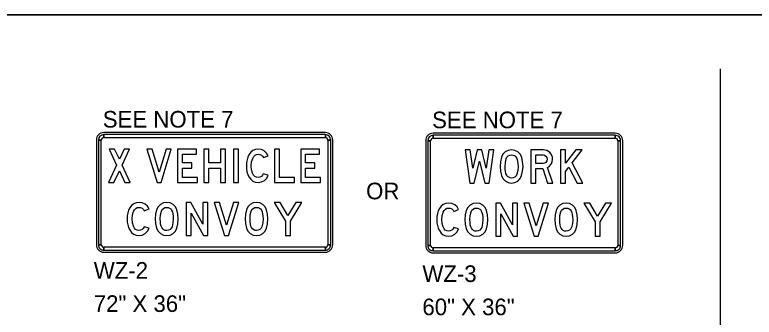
# Model space of a CAD drawing. Extents: x 1416408 to 1429341, y 372694 to 383211.
# Drawn here: x 1427672.1 to 1428119.8, y 374297 to 374479.9 of the extents above; entities that cross this region are included whole.
import ezdxf

# ---------------------------------------------------------------- set-up
doc = ezdxf.new("R2010")
doc.units = 0
for name, color, linetype in [('Default', 7, 'Continuous'), ('DSN_DRFT_Junk-No-Plot', 7, 'Continuous'), ('Working Level 1', 7, 'Continuous')]:
    doc.layers.add(name, color=color, linetype=linetype)

msp = doc.modelspace()

# ---------------------------------------------------------------- linework, layer by layer
at = {"layer": 'Default'}
for points in [[(1426234.86, 374479.9), (1426234.86, 372693.86), (1428995.11, 372693.86), (1428995.11, 374479.9)], [(1426234.86, 374479.9), (1426234.86, 372693.86), (1428995.11, 372693.86), (1428995.11, 374479.9)], [(1426234.86, 374479.9), (1428995.11, 374479.9), (1428995.11, 372693.86), (1426234.86, 372693.86)], [(1426234.86, 374479.9), (1426234.86, 372693.86), (1428995.11, 372693.86), (1428995.11, 374479.9)]]:
    msp.add_lwpolyline(points, close=True, dxfattribs=at)
at = {"layer": 'DSN_DRFT_Junk-No-Plot'}
msp.add_lwpolyline([(1426234.86, 374479.9), (1428995.11, 374479.9), (1428995.11, 372693.86), (1426234.86, 372693.86)], close=True, dxfattribs=at)
at = {"layer": 'Working Level 1'}
for p, q in [((1428099.08, 374447.3), (1428099.08, 372727.17)), ((1427860.12, 374408.67), (1427725.97, 374408.67)), ((1428035.67, 374408.28), (1427925.37, 374408.28)), ((1427721.5, 374404.15), (1427721.5, 374340.86)), ((1427722.74, 374404.15), (1427724.48, 374404.15)), ((1427725.97, 374405.66), (1427725.97, 374407.42)), ((1427860.12, 374407.42), (1427860.12, 374405.66)), ((1427861.61, 374404.15), (1427863.35, 374404.15)), ((1427864.59, 374340.86), (1427864.59, 374404.15)), ((1427920.9, 374403.76), (1427920.9, 374340.47)), ((1427922.14, 374403.76), (1427923.88, 374403.76)), ((1427925.37, 374405.27), (1427925.37, 374407.02)), ((1428035.67, 374407.02), (1428035.67, 374405.27)), ((1428037.16, 374403.76), (1428038.9, 374403.76)), ((1428040.14, 374340.47), (1428040.14, 374403.76)), ((1427724.48, 374340.86), (1427722.74, 374340.86)), ((1427863.35, 374340.86), (1427861.61, 374340.86)), ((1427725.97, 374337.6), (1427725.97, 374339.35)), ((1427725.97, 374336.34), (1427860.12, 374336.34)), ((1427860.12, 374339.35), (1427860.12, 374337.6)), ((1427923.88, 374340.47), (1427922.14, 374340.47)), ((1427925.37, 374337.2), (1427925.37, 374338.96)), ((1428035.67, 374338.96), (1428035.67, 374337.2)), ((1428038.9, 374340.47), (1428037.16, 374340.47)), ((1427925.37, 374335.95), (1428035.67, 374335.95))]:
    msp.add_line(p, q, dxfattribs=at)
for points in [[(1427722.74, 374404.15), (1427722.74, 374340.86), (1427724.48, 374340.86), (1427724.48, 374404.15), (1427722.74, 374404.15)], [(1427860.12, 374407.42), (1427725.97, 374407.42), (1427725.97, 374405.66), (1427860.12, 374405.66), (1427860.12, 374407.42)], [(1427863.35, 374340.86), (1427863.35, 374404.15), (1427861.61, 374404.15), (1427861.61, 374340.86), (1427863.35, 374340.86)], [(1427922.14, 374403.76), (1427922.14, 374340.47), (1427923.88, 374340.47), (1427923.88, 374403.76), (1427922.14, 374403.76)], [(1428035.67, 374407.02), (1427925.37, 374407.02), (1427925.37, 374405.27), (1428035.67, 374405.27), (1428035.67, 374407.02)], [(1428038.9, 374340.47), (1428038.9, 374403.76), (1428037.16, 374403.76), (1428037.16, 374340.47), (1428038.9, 374340.47)], [(1427742.03, 374378.53), (1427737.08, 374389.05), (1427741.62, 374398.62), (1427738.3, 374398.62), (1427735.42, 374392.56), (1427732.56, 374398.62), (1427729.23, 374398.62), (1427733.75, 374389.03), (1427728.77, 374378.53), (1427732.09, 374378.53), (1427735.4, 374385.52), (1427738.71, 374378.53)], [(1427766.85, 374398.62), (1427763.71, 374398.62), (1427759.45, 374384.74), (1427755.19, 374398.62), (1427752.05, 374398.62), (1427758.21, 374378.53), (1427760.68, 374378.53)], [(1427782.7, 374381.57), (1427773.68, 374381.57), (1427773.68, 374387.25), (1427779.31, 374387.25), (1427779.31, 374390.28), (1427773.68, 374390.28), (1427773.68, 374395.59), (1427782.09, 374395.59), (1427782.09, 374398.62), (1427770.69, 374398.62), (1427770.69, 374378.53), (1427782.7, 374378.53)], [(1427799.64, 374378.53), (1427799.64, 374398.62), (1427796.65, 374398.62), (1427796.65, 374390.28), (1427789.52, 374390.28), (1427789.52, 374398.62), (1427786.52, 374398.62), (1427786.52, 374378.53), (1427789.52, 374378.53), (1427789.52, 374387.25), (1427796.65, 374387.25), (1427796.65, 374378.53)], [(1427807.53, 374378.53), (1427807.53, 374398.62), (1427804.53, 374398.62), (1427804.53, 374378.53)], [(1427825.56, 374382.99), (1427822.55, 374383.76), (1427822.11, 374382.88), (1427821.38, 374382.18), (1427820.45, 374381.72), (1427819.42, 374381.57), (1427818.37, 374381.72), (1427817.47, 374382.21), (1427816.72, 374383), (1427816.11, 374384.12), (1427815.49, 374386.19), (1427815.3, 374388.58), (1427815.5, 374390.98), (1427816.13, 374393.05), (1427816.76, 374394.16), (1427817.54, 374394.95), (1427818.45, 374395.43), (1427819.51, 374395.59), (1427820.5, 374395.45), (1427821.41, 374395.04), (1427822.16, 374394.38), (1427822.68, 374393.54), (1427825.56, 374394.68), (1427824.59, 374396.29), (1427823.17, 374397.55), (1427821.45, 374398.35), (1427819.56, 374398.62), (1427817.81, 374398.41), (1427816.29, 374397.78), (1427814.98, 374396.73), (1427813.9, 374395.27), (1427813.19, 374393.82), (1427812.7, 374392.23), (1427812.4, 374390.48), (1427812.3, 374388.59), (1427812.39, 374386.7), (1427812.69, 374384.96), (1427813.18, 374383.37), (1427813.88, 374381.92), (1427814.94, 374380.43), (1427816.23, 374379.38), (1427817.73, 374378.74), (1427819.46, 374378.53), (1427821.48, 374378.84), (1427823.3, 374379.77), (1427824.72, 374381.2)], [(1427841.39, 374378.53), (1427841.39, 374381.57), (1427832.37, 374381.57), (1427832.37, 374398.62), (1427829.38, 374398.62), (1427829.38, 374378.53)], [(1427857.23, 374381.57), (1427848.21, 374381.57), (1427848.21, 374387.25), (1427853.84, 374387.25), (1427853.84, 374390.28), (1427848.21, 374390.28), (1427848.21, 374395.59), (1427856.62, 374395.59), (1427856.62, 374398.62), (1427845.21, 374398.62), (1427845.21, 374378.53), (1427857.23, 374378.53)], [(1427962.08, 374398.23), (1427959.05, 374398.23), (1427957.52, 374387.23), (1427954.89, 374398.23), (1427951.99, 374398.23), (1427949.37, 374387.21), (1427947.85, 374398.23), (1427944.81, 374398.23), (1427947.59, 374378.14), (1427950.3, 374378.14), (1427953.44, 374391.36), (1427956.59, 374378.14), (1427959.29, 374378.14)], [(1427979.8, 374388.2), (1427979.59, 374391.07), (1427978.99, 374393.75), (1427978.09, 374395.56), (1427976.67, 374397), (1427974.87, 374397.92), (1427972.85, 374398.23), (1427970.83, 374397.92), (1427969.04, 374397), (1427967.62, 374395.56), (1427966.73, 374393.73), (1427966.12, 374391.05), (1427965.93, 374388.2), (1427966.12, 374385.35), (1427966.73, 374382.66), (1427967.62, 374380.84), (1427969.04, 374379.4), (1427970.83, 374378.45), (1427972.85, 374378.14), (1427974.87, 374378.45), (1427976.66, 374379.38), (1427978.07, 374380.81), (1427978.97, 374382.63), (1427979.59, 374385.32)], [(1427976.8, 374388.19), (1427976.62, 374385.75), (1427976.1, 374383.48), (1427975.61, 374382.53), (1427974.87, 374381.8), (1427973.93, 374381.33), (1427972.87, 374381.17), (1427971.94, 374381.28), (1427971.14, 374381.61), (1427970.46, 374382.16), (1427969.91, 374382.93), (1427969.47, 374383.91), (1427969.17, 374385.12), (1427968.98, 374386.54), (1427968.92, 374388.19), (1427969.1, 374390.62), (1427969.63, 374392.88), (1427970.1, 374393.83), (1427970.85, 374394.57), (1427971.79, 374395.04), (1427972.87, 374395.2), (1427973.79, 374395.09), (1427974.58, 374394.76), (1427975.26, 374394.21), (1427975.81, 374393.45), (1427976.24, 374392.46), (1427976.55, 374391.26), (1427976.73, 374389.83)], [(1427997.82, 374378.14), (1427994.68, 374387.52), (1427995.91, 374388.39), (1427996.86, 374389.6), (1427997.47, 374391.04), (1427997.68, 374392.59), (1427997.57, 374393.71), (1427997.26, 374394.74), (1427996.75, 374395.7), (1427996.03, 374396.57), (1427995.15, 374397.3), (1427994.2, 374397.82), (1427993.17, 374398.13), (1427992.06, 374398.23), (1427984.56, 374398.23), (1427984.56, 374378.14), (1427987.56, 374378.14), (1427987.56, 374386.86), (1427991.72, 374386.86), (1427994.66, 374378.14)], [(1427987.56, 374389.89), (1427987.56, 374395.2), (1427991.93, 374395.2), (1427992.88, 374395), (1427993.69, 374394.41), (1427994.23, 374393.55), (1427994.42, 374392.55), (1427994.23, 374391.52), (1427993.69, 374390.67), (1427992.88, 374390.08), (1427991.93, 374389.89)], [(1428016.03, 374378.14), (1428009.57, 374390.38), (1428015.55, 374398.23), (1428011.76, 374398.23), (1428005.57, 374390.09), (1428005.57, 374398.23), (1428002.57, 374398.23), (1428002.57, 374378.14), (1428005.57, 374378.14), (1428005.57, 374385.12), (1428007.57, 374387.74), (1428012.63, 374378.14)], [(1427753.36, 374350.84), (1427750.36, 374351.61), (1427749.91, 374350.73), (1427749.19, 374350.03), (1427748.25, 374349.57), (1427747.22, 374349.42), (1427746.17, 374349.58), (1427745.28, 374350.06), (1427744.52, 374350.86), (1427743.91, 374351.98), (1427743.3, 374354.04), (1427743.1, 374356.43), (1427743.3, 374358.84), (1427743.94, 374360.9), (1427744.56, 374362.01), (1427745.34, 374362.8), (1427746.25, 374363.28), (1427747.32, 374363.44), (1427748.31, 374363.3), (1427749.21, 374362.89), (1427749.97, 374362.23), (1427750.48, 374361.39), (1427753.36, 374362.53), (1427752.39, 374364.14), (1427750.97, 374365.4), (1427749.25, 374366.2), (1427747.36, 374366.48), (1427745.61, 374366.26), (1427744.09, 374365.64), (1427742.78, 374364.59), (1427741.7, 374363.13), (1427741, 374361.67), (1427740.5, 374360.08), (1427740.2, 374358.33), (1427740.1, 374356.44), (1427740.19, 374354.55), (1427740.49, 374352.81), (1427740.98, 374351.22), (1427741.68, 374349.77), (1427742.74, 374348.29), (1427744.03, 374347.23), (1427745.54, 374346.59), (1427747.26, 374346.39), (1427749.28, 374346.69), (1427751.1, 374347.62), (1427752.52, 374349.05)], [(1427771.05, 374356.44), (1427770.85, 374359.31), (1427770.24, 374361.99), (1427769.35, 374363.8), (1427767.92, 374365.24), (1427766.12, 374366.16), (1427764.1, 374366.48), (1427762.08, 374366.16), (1427760.29, 374365.24), (1427758.88, 374363.8), (1427757.99, 374361.98), (1427757.38, 374359.29), (1427757.18, 374356.44), (1427757.38, 374353.59), (1427757.99, 374350.9), (1427758.88, 374349.08), (1427760.29, 374347.64), (1427762.08, 374346.7), (1427764.1, 374346.39), (1427766.12, 374346.69), (1427767.91, 374347.62), (1427769.33, 374349.05), (1427770.23, 374350.87), (1427770.84, 374353.56)], [(1427768.05, 374356.43), (1427767.87, 374353.99), (1427767.35, 374351.72), (1427766.87, 374350.77), (1427766.12, 374350.04), (1427765.19, 374349.57), (1427764.13, 374349.42), (1427763.2, 374349.52), (1427762.39, 374349.86), (1427761.71, 374350.4), (1427761.16, 374351.17), (1427760.73, 374352.15), (1427760.42, 374353.36), (1427760.24, 374354.78), (1427760.18, 374356.43), (1427760.35, 374358.86), (1427760.88, 374361.12), (1427761.35, 374362.07), (1427762.1, 374362.81), (1427763.04, 374363.28), (1427764.13, 374363.44), (1427765.04, 374363.33), (1427765.84, 374363.01), (1427766.51, 374362.46), (1427767.07, 374361.69), (1427767.49, 374360.7), (1427767.8, 374359.5), (1427767.99, 374358.07)], [(1427788.93, 374346.39), (1427788.93, 374366.48), (1427785.93, 374366.48), (1427785.93, 374353.27), (1427778.69, 374366.48), (1427775.81, 374366.48), (1427775.81, 374346.39), (1427778.81, 374346.39), (1427778.81, 374360.02), (1427786.29, 374346.39)], [(1427807.69, 374366.48), (1427804.55, 374366.48), (1427800.28, 374352.59), (1427796.02, 374366.48), (1427792.89, 374366.48), (1427799.05, 374346.39), (1427801.51, 374346.39)], [(1427825.39, 374356.44), (1427825.19, 374359.31), (1427824.58, 374361.99), (1427823.69, 374363.8), (1427822.26, 374365.24), (1427820.46, 374366.16), (1427818.44, 374366.48), (1427816.42, 374366.16), (1427814.64, 374365.24), (1427813.22, 374363.8), (1427812.33, 374361.98), (1427811.72, 374359.29), (1427811.52, 374356.44), (1427811.72, 374353.59), (1427812.33, 374350.9), (1427813.22, 374349.08), (1427814.64, 374347.64), (1427816.42, 374346.7), (1427818.44, 374346.39), (1427820.46, 374346.69), (1427822.25, 374347.62), (1427823.67, 374349.05), (1427824.57, 374350.87), (1427825.18, 374353.56)], [(1427822.39, 374356.43), (1427822.22, 374353.99), (1427821.69, 374351.72), (1427821.21, 374350.77), (1427820.46, 374350.04), (1427819.53, 374349.57), (1427818.47, 374349.42), (1427817.54, 374349.52), (1427816.73, 374349.86), (1427816.05, 374350.4), (1427815.5, 374351.17), (1427815.07, 374352.15), (1427814.76, 374353.36), (1427814.58, 374354.78), (1427814.52, 374356.43), (1427814.69, 374358.86), (1427815.22, 374361.12), (1427815.7, 374362.07), (1427816.44, 374362.81), (1427817.38, 374363.28), (1427818.47, 374363.44), (1427819.38, 374363.33), (1427820.18, 374363.01), (1427820.85, 374362.46), (1427821.41, 374361.69), (1427821.84, 374360.7), (1427822.15, 374359.5), (1427822.33, 374358.07)], [(1427845.88, 374366.48), (1427842.35, 374366.48), (1427837.48, 374358.46), (1427832.71, 374366.48), (1427829.22, 374366.48), (1427835.97, 374355.19), (1427835.97, 374346.39), (1427838.97, 374346.39), (1427838.97, 374355.11)], [(1427940.84, 374350.45), (1427937.83, 374351.22), (1427937.39, 374350.34), (1427936.66, 374349.64), (1427935.73, 374349.18), (1427934.69, 374349.03), (1427933.65, 374349.19), (1427932.75, 374349.67), (1427932, 374350.47), (1427931.39, 374351.58), (1427930.77, 374353.65), (1427930.58, 374356.04), (1427930.78, 374358.44), (1427931.41, 374360.51), (1427932.04, 374361.62), (1427932.81, 374362.41), (1427933.73, 374362.89), (1427934.79, 374363.05), (1427935.78, 374362.91), (1427936.69, 374362.5), (1427937.44, 374361.84), (1427937.96, 374361), (1427940.84, 374362.14), (1427939.87, 374363.75), (1427938.45, 374365.01), (1427936.73, 374365.81), (1427934.84, 374366.08), (1427933.09, 374365.87), (1427931.56, 374365.25), (1427930.26, 374364.2), (1427929.18, 374362.73), (1427928.47, 374361.28), (1427927.97, 374359.69), (1427927.68, 374357.94), (1427927.58, 374356.05), (1427927.67, 374354.16), (1427927.97, 374352.42), (1427928.46, 374350.83), (1427929.16, 374349.38), (1427930.22, 374347.9), (1427931.51, 374346.84), (1427933.01, 374346.2), (1427934.74, 374345.99), (1427936.76, 374346.3), (1427938.58, 374347.23), (1427940, 374348.66)], [(1427958.53, 374356.05), (1427958.32, 374358.92), (1427957.72, 374361.6), (1427956.82, 374363.41), (1427955.4, 374364.85), (1427953.6, 374365.77), (1427951.58, 374366.08), (1427949.56, 374365.77), (1427947.77, 374364.85), (1427946.35, 374363.41), (1427945.46, 374361.58), (1427944.85, 374358.9), (1427944.66, 374356.05), (1427944.85, 374353.2), (1427945.46, 374350.51), (1427946.35, 374348.69), (1427947.77, 374347.25), (1427949.56, 374346.31), (1427951.58, 374345.99), (1427953.6, 374346.3), (1427955.39, 374347.23), (1427956.8, 374348.66), (1427957.7, 374350.48), (1427958.32, 374353.17)], [(1427955.53, 374356.04), (1427955.35, 374353.6), (1427954.83, 374351.33), (1427954.34, 374350.38), (1427953.6, 374349.65), (1427952.66, 374349.18), (1427951.6, 374349.03), (1427950.67, 374349.13), (1427949.87, 374349.46), (1427949.19, 374350.01), (1427948.64, 374350.78), (1427948.2, 374351.76), (1427947.9, 374352.97), (1427947.71, 374354.39), (1427947.65, 374356.04), (1427947.83, 374358.47), (1427948.36, 374360.73), (1427948.83, 374361.68), (1427949.58, 374362.42), (1427950.52, 374362.89), (1427951.6, 374363.05), (1427952.52, 374362.94), (1427953.31, 374362.61), (1427953.99, 374362.06), (1427954.54, 374361.3), (1427954.97, 374360.31), (1427955.28, 374359.11), (1427955.46, 374357.68)], [(1427976.41, 374345.99), (1427976.41, 374366.08), (1427973.41, 374366.08), (1427973.41, 374352.88), (1427966.17, 374366.08), (1427963.29, 374366.08), (1427963.29, 374345.99), (1427966.29, 374345.99), (1427966.29, 374359.62), (1427973.76, 374345.99)], [(1427995.16, 374366.08), (1427992.02, 374366.08), (1427987.76, 374352.2), (1427983.5, 374366.08), (1427980.37, 374366.08), (1427986.52, 374345.99), (1427988.99, 374345.99)], [(1428012.87, 374356.05), (1428012.66, 374358.92), (1428012.06, 374361.6), (1428011.17, 374363.41), (1428009.74, 374364.85), (1428007.94, 374365.77), (1428005.92, 374366.08), (1428003.9, 374365.77), (1428002.11, 374364.85), (1428000.69, 374363.41), (1427999.8, 374361.58), (1427999.2, 374358.9), (1427999, 374356.05), (1427999.2, 374353.2), (1427999.8, 374350.51), (1428000.69, 374348.69), (1428002.11, 374347.25), (1428003.9, 374346.31), (1428005.92, 374345.99), (1428007.94, 374346.3), (1428009.73, 374347.23), (1428011.15, 374348.66), (1428012.04, 374350.48), (1428012.66, 374353.17)], [(1428009.87, 374356.04), (1428009.69, 374353.6), (1428009.17, 374351.33), (1428008.69, 374350.38), (1428007.94, 374349.65), (1428007, 374349.18), (1428005.94, 374349.03), (1428005.01, 374349.13), (1428004.21, 374349.46), (1428003.53, 374350.01), (1428002.98, 374350.78), (1428002.55, 374351.76), (1428002.24, 374352.97), (1428002.05, 374354.39), (1428002, 374356.04), (1428002.17, 374358.47), (1428002.7, 374360.73), (1428003.17, 374361.68), (1428003.92, 374362.42), (1428004.86, 374362.89), (1428005.94, 374363.05), (1428006.86, 374362.94), (1428007.65, 374362.61), (1428008.33, 374362.06), (1428008.88, 374361.3), (1428009.31, 374360.31), (1428009.62, 374359.11), (1428009.8, 374357.68)], [(1428033.35, 374366.08), (1428029.83, 374366.08), (1428024.96, 374358.06), (1428020.19, 374366.08), (1428016.7, 374366.08), (1428023.44, 374354.79), (1428023.44, 374345.99), (1428026.44, 374345.99), (1428026.44, 374354.71)], [(1427725.97, 374337.6), (1427860.12, 374337.6), (1427860.12, 374339.35), (1427725.97, 374339.35), (1427725.97, 374337.6)], [(1427925.37, 374337.2), (1428035.67, 374337.2), (1428035.67, 374338.96), (1427925.37, 374338.96), (1427925.37, 374337.2)]]:
    msp.add_lwpolyline(points, close=True, dxfattribs=at)
for centre, major_axis, start_param, end_param in [((1427725.97, 374404.15), (0, 4.52), 0.000004, 1.570794), ((1427860.12, 374404.15), (0, 4.52), 4.712389, 6.283189), ((1427925.37, 374403.76), (0, 4.52), 0.000004, 1.570794), ((1428035.67, 374403.76), (0, 4.52), 4.712389, 6.283189), ((1427725.97, 374404.15), (0, 3.27), 0.000004, 1.570794), ((1427725.97, 374404.15), (0, 1.51), 0.000004, 1.570794), ((1427860.12, 374404.15), (0, 3.27), 4.712389, 6.283189), ((1427860.12, 374404.15), (0, 1.51), 4.712389, 6.283189), ((1427925.37, 374403.76), (0, 3.27), 0.000004, 1.570794), ((1427925.37, 374403.76), (0, 1.51), 0.000004, 1.570794), ((1428035.67, 374403.76), (0, 3.27), 4.712389, 6.283189), ((1428035.67, 374403.76), (0, 1.51), 4.712389, 6.283189), ((1427725.97, 374340.86), (0, 4.52), 1.570794, 3.141594), ((1427725.97, 374340.86), (0, 3.27), 1.570794, 3.141594), ((1427725.97, 374340.86), (0, 1.51), 1.570794, 3.141594), ((1427860.12, 374340.86), (0, 4.52), 3.141594, 4.712394), ((1427860.12, 374340.86), (0, 3.27), 3.141594, 4.712394), ((1427860.12, 374340.86), (0, 1.51), 3.141594, 4.712394), ((1427925.37, 374340.47), (0, 4.52), 1.570794, 3.141594), ((1427925.37, 374340.47), (0, 3.27), 1.570794, 3.141594), ((1427925.37, 374340.47), (0, 1.51), 1.570794, 3.141594), ((1428035.67, 374340.47), (0, 4.52), 3.141594, 4.712394), ((1428035.67, 374340.47), (0, 3.27), 3.141594, 4.712394), ((1428035.67, 374340.47), (0, 1.51), 3.141594, 4.712394)]:
    msp.add_ellipse(centre, major_axis=major_axis, ratio=0.989089, start_param=start_param, end_param=end_param, dxfattribs=at)

# ---------------------------------------------------------------- texts
for p in [(1427725.37, 374411.7), (1427924.77, 374411.31)]:
    msp.add_text('SEE NOTE 7 ', height=10.0465, dxfattribs=at).set_placement(p)
for s, p in [('OR', (1427884.8, 374368.32)), ('WZ-2', (1427719.92, 374320.29)), ('WZ-3', (1427918.89, 374318.32)), ('72" X 36"', (1427719.92, 374300.2)), ('60" X 36"', (1427918.89, 374298.23))]:
    msp.add_text(s, height=10.046, rotation=0, dxfattribs=at).set_placement(p)

doc.saveas('drawing.dxf')
